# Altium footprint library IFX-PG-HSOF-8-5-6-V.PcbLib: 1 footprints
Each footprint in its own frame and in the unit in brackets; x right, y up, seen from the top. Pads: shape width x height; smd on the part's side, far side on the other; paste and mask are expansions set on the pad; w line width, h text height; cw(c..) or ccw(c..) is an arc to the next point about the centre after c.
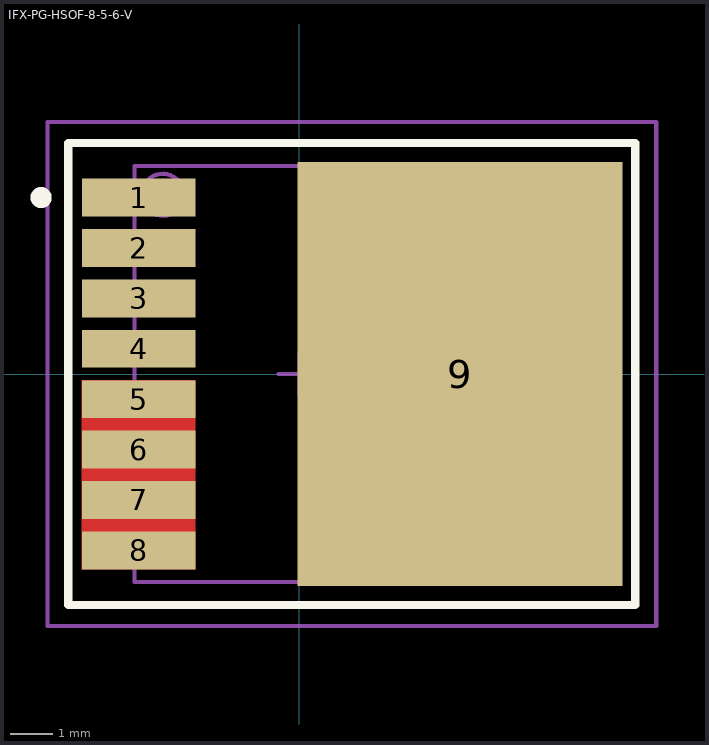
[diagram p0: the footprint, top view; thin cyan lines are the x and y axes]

## IFX-PG-HSOF-8-5-6-V [mm] "PG-HSOF-8, SMD, 1.2 mm pitch, 9 pin, 10.375 mm L X 9.90 mm W X 2.30 mm H body"
height 2.3
pads (9):
  rect 2.7x0.9 smd paste-0.45 mask-0.05: 1(-3.827,4.2) 2(-3.827,3) 3(-3.827,1.8) 4(-3.827,0.6)
  rect 2.7x0.9 smd paste-1.3 mask-0.45: 5(-3.827,-0.6) 6(-3.827,-1.8) 7(-3.827,-3) 8(-3.827,-4.2)
  rect 7.743x10.1 smd paste-5.05 mask-5.05: 9(3.827,0)
Top Layer:
  region: -5.176,-0.15 -2.476,-0.15 -2.476,-4.65 -5.176,-4.65
Top Overlay:
  circle w0.25: c-6.15,4.2 r0.125
  lines w0.2: -5.5,-5.5 -5.5,5.5 8,5.5 8,-5.5 -5.5,-5.5
Top Paste:
  region: 1.528,-0.25 1.528,-4.25 0.328,-4.25 0.328,-0.25
  region: 3.028,-0.25 3.028,-4.25 1.828,-4.25 1.828,-0.25
  region: 4.528,-0.25 4.528,-3.67 3.328,-3.67 3.328,-0.25
  region: 6.028,-0.25 6.028,-3.67 4.828,-3.67 4.828,-0.25
  region: 1.528,4.25 1.528,0.25 0.328,0.25 0.328,4.25
  region: 3.028,4.25 3.028,0.25 1.828,0.25 1.828,4.25
  region: 4.528,3.67 4.528,0.25 3.328,0.25 3.328,3.67
  region: 6.028,3.67 6.028,0.25 4.828,0.25 4.828,3.67
  region: 7.528,-0.25 7.528,-4.25 6.328,-4.25 6.328,-0.25
  region: 7.528,4.25 7.528,0.25 6.328,0.25 6.328,4.25
  region: -2.877,4.55 -2.877,3.85 -5.077,3.85 -5.077,4.55
  region: -2.877,3.35 -2.877,2.65 -5.077,2.65 -5.077,3.35
  region: -2.877,2.15 -2.877,1.45 -5.077,1.45 -5.077,2.15
  region: -2.877,0.95 -2.877,0.25 -5.077,0.25 -5.077,0.95
  region: -5.079,-3.35 -5.077,-3.35 -2.579,-3.35 -2.579,-2.65 -5.079,-2.65
  region: -5.079,-2.15 -5.077,-2.15 -2.579,-2.15 -2.579,-1.45 -5.079,-1.45
  region: -5.079,-0.95 -5.077,-0.95 -2.579,-0.95 -2.579,-0.25 -5.079,-0.25
  region: -5.079,-4.55 -5.077,-4.55 -2.579,-4.55 -2.579,-3.85 -5.079,-3.85
Top Solder:
  region: -2.527,-0.2 -2.527,-4.6 -5.127,-4.6 -5.127,-3.8 -3.422,-3.8 -3.422,-3.4 -5.127,-3.4 -5.127,-2.6 -3.422,-2.6 -3.422,-2.2 -5.127,-2.2 -5.127,-1.4 -3.422,-1.4 -3.422,-1 -5.127,-1 -5.127,-0.2
  region: 0.006,4.83 3.609,4.83 3.609,4.831 3.609,4.351 6.354,4.351 6.354,5.001 7.649,5.001 7.649,-5 6.354,-5 6.354,-4.35 3.609,-4.35 3.609,-4.83 0.006,-4.83
M3 (ASY_Text_Top):
  text ".DESIGNATOR" at -3.643,-0.385 h1.2
M13 (CMP_Body_OTL_Top):
  circle w0.1: c-3.251,4.267 r0.5
  lines w0.1: -3.926,-4.95 -3.926,4.95 6.449,4.95 6.449,-4.95 -3.926,-4.95
M15 (CMP_Courtyard_Top):
  lines w0.1: -0.5,0 0.5,0 ; 0,-0.5 0,0.5 ; -6,-6 -6,6 8.5,6 8.5,-6 -6,-6
3D body "PG-HSOF-8-(5-6).STEP": height 2.3, standoff 0, extent -4.576,-4.95 7.099,4.95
